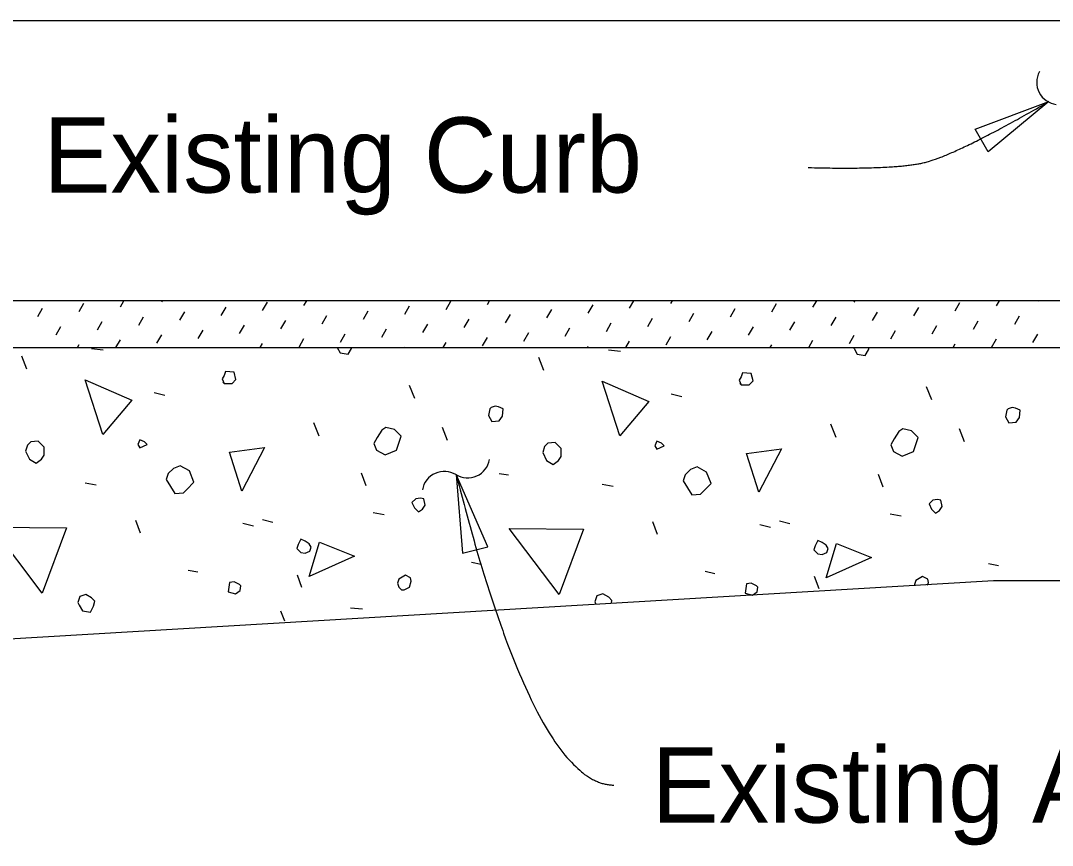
# Model space of a CAD drawing. Extents: x 0 to 41.1, y 0 to 25.9.
# Drawn here: x 29.229 to 31.992, y 5.252 to 7.46 of the extents above; entities that cross this region are included whole.
import ezdxf

# ---------------------------------------------------------------- set-up
doc = ezdxf.new("R2010")
doc.units = 0
for name, color, linetype in [('Dimension', 7, 'Continuous'), ('ExistSuperStruct', 7, 'Continuous'), ('Miscellaneous', 7, 'Continuous'), ('TextStructures', 7, 'Continuous')]:
    doc.layers.add(name, color=color, linetype=linetype)

msp = doc.modelspace()

# ---------------------------------------------------------------- linework, layer by layer
at = {"layer": 'Dimension'}
for points in [[(31.9826, 7.2434), (31.8199, 7.1087), (31.7846, 7.1698)], [(30.3947, 6.2447), (30.4118, 6.0341), (30.4801, 6.0515)]]:
    msp.add_lwpolyline(points, close=True, dxfattribs=at)
for centre, start, end in [((32.0093, 7.2949), 151.5267, 263.2539), ((30.4256, 6.2953), 238.4384, 350.1656), ((30.3632, 6.1937), 58.4384, 170.1656)]:
    msp.add_arc(centre, 0.0596, start, end, dxfattribs=at)
for points in [[(31.338, 7.0666), (31.5548, 7.0609), (31.7259, 7.0951), (31.9826, 7.2435)], [(30.3951, 6.2447), (30.6063, 5.4135), (30.8176, 5.4135)]]:
    msp.add_open_spline(points, degree=2, dxfattribs=at)
at = {"layer": 'ExistSuperStruct'}
for p, q in [((26.6139, 7.4599), (34.561, 7.4599)), ((37.3622, 6.71), (26.6139, 6.71)), ((26.6139, 6.585), (37.3622, 6.585)), ((31.8338, 5.9599), (27.6138, 5.7099)), ((37.3622, 5.9599), (31.8338, 5.9599))]:
    msp.add_line(p, q, dxfattribs=at)
at = {"layer": 'Miscellaneous'}
for p, q in [((29.2746, 6.6679), (29.2875, 6.6903)), ((29.3852, 6.6809), (29.3982, 6.7033)), ((29.4958, 6.6938), (29.5052, 6.71)), ((29.6065, 6.7068), (29.6083, 6.71)), ((29.7659, 6.6709), (29.7789, 6.6933)), ((29.8766, 6.6839), (29.8895, 6.7063)), ((29.9872, 6.6969), (29.9948, 6.71)), ((30.0978, 6.7098), (30.0979, 6.71)), ((30.2573, 6.6739), (30.2702, 6.6963)), ((30.3679, 6.6869), (30.3809, 6.7093)), ((30.4786, 6.6999), (30.4844, 6.71)), ((30.7487, 6.677), (30.7616, 6.6994)), ((30.8593, 6.6899), (30.8709, 6.71)), ((30.9699, 6.7029), (30.974, 6.71)), ((31.1294, 6.667), (31.1423, 6.6894)), ((31.24, 6.68), (31.253, 6.7024)), ((31.3506, 6.693), (31.3605, 6.71)), ((31.4613, 6.7059), (31.4637, 6.71)), ((31.6207, 6.67), (31.6337, 6.6924)), ((31.7314, 6.683), (31.7443, 6.7054)), ((31.842, 6.696), (31.8502, 6.71)), ((31.9526, 6.7089), (31.9533, 6.71)), ((29.5447, 6.645), (29.5576, 6.6674)), ((29.6553, 6.658), (29.6683, 6.6804)), ((30.036, 6.648), (30.049, 6.6704)), ((30.1467, 6.661), (30.1596, 6.6834)), ((30.4168, 6.6381), (30.4297, 6.6605)), ((30.5274, 6.651), (30.5403, 6.6734)), ((30.638, 6.664), (30.651, 6.6864)), ((30.9081, 6.6411), (30.9211, 6.6635)), ((31.0188, 6.6541), (31.0317, 6.6765)), ((31.3995, 6.6441), (31.4124, 6.6665)), ((31.5101, 6.6571), (31.5231, 6.6795)), ((31.8908, 6.6471), (31.9038, 6.6695)), ((29.3234, 6.6191), (29.3364, 6.6415)), ((29.434, 6.632), (29.447, 6.6544)), ((29.8148, 6.6221), (29.8277, 6.6445)), ((29.9254, 6.6351), (29.9384, 6.6574)), ((30.1955, 6.6121), (30.2085, 6.6345)), ((30.3061, 6.6251), (30.3191, 6.6475)), ((30.6869, 6.6152), (30.6998, 6.6376)), ((30.7975, 6.6281), (30.8104, 6.6505)), ((31.1782, 6.6182), (31.1912, 6.6406)), ((31.2889, 6.6312), (31.3018, 6.6535)), ((31.6696, 6.6212), (31.6825, 6.6436)), ((31.7802, 6.6342), (31.7932, 6.6566)), ((29.4839, 6.585), (29.4958, 6.6056)), ((29.5935, 6.5962), (29.6065, 6.6186)), ((29.7041, 6.6091), (29.7171, 6.6315)), ((29.9742, 6.5862), (29.9872, 6.6086)), ((30.0849, 6.5992), (30.0978, 6.6216)), ((30.4656, 6.5892), (30.4786, 6.6116)), ((30.5762, 6.6022), (30.5892, 6.6246)), ((30.957, 6.5923), (30.9699, 6.6147)), ((31.0676, 6.6052), (31.0805, 6.6276)), ((31.3392, 6.585), (31.3506, 6.6047)), ((31.4483, 6.5953), (31.4613, 6.6177)), ((31.559, 6.6082), (31.5719, 6.6306)), ((31.8291, 6.5853), (31.842, 6.6077)), ((31.9397, 6.5983), (31.9526, 6.6207)), ((29.3807, 6.585), (29.3852, 6.5926)), ((29.4182, 6.5825), (29.45, 6.579)), ((29.8704, 6.585), (29.8766, 6.5957)), ((30.2569, 6.585), (30.2573, 6.5857)), ((30.36, 6.585), (30.3679, 6.5987)), ((30.7465, 6.585), (30.7487, 6.5887)), ((30.8029, 6.579), (30.8347, 6.5755)), ((30.8496, 6.585), (30.8593, 6.6017)), ((31.2361, 6.585), (31.24, 6.5917)), ((31.7257, 6.585), (31.7314, 6.5948)), ((29.2456, 6.5266), (29.2314, 6.5619)), ((30.6302, 6.5231), (30.6161, 6.5584)), ((30.2844, 6.4482), (30.2702, 6.4835)), ((31.6691, 6.4446), (31.6549, 6.48)), ((29.5861, 6.4641), (29.6144, 6.457)), ((30.9708, 6.4606), (30.9991, 6.4535)), ((30.0281, 6.3474), (30.0139, 6.3828)), ((30.3721, 6.3357), (30.358, 6.371)), ((31.4127, 6.3439), (31.3986, 6.3792)), ((31.7568, 6.3321), (31.7427, 6.3675)), ((30.1536, 6.2148), (30.1412, 6.2484)), ((30.51, 6.2473), (30.5348, 6.2437)), ((31.5382, 6.2113), (31.5259, 6.2449)), ((29.4011, 6.2225), (29.4312, 6.2172)), ((30.7858, 6.219), (30.8159, 6.2137)), ((30.1724, 6.143), (30.2024, 6.1377)), ((31.5571, 6.1394), (31.5871, 6.1341)), ((29.5496, 6.0882), (29.5372, 6.1218)), ((29.8236, 6.1147), (29.8519, 6.1076)), ((29.876, 6.1247), (29.9043, 6.1176)), ((30.9343, 6.0846), (30.9219, 6.1182)), ((31.2083, 6.1112), (31.2366, 6.1041)), ((31.2607, 6.1211), (31.289, 6.1141)), ((30.4358, 6.0104), (30.4623, 6.0051)), ((31.8205, 6.0069), (31.847, 6.0016)), ((29.6769, 5.9892), (29.7034, 5.9839)), ((29.9821, 5.9421), (29.9697, 5.9757)), ((31.0616, 5.9857), (31.0881, 5.9803)), ((31.3668, 5.9385), (31.3544, 5.9721)), ((30.1123, 5.8884), (30.1441, 5.8849)), ((29.9361, 5.8525), (29.9255, 5.879))]:
    msp.add_line(p, q, dxfattribs=at)
for points in [[(30.0764, 6.585), (30.0846, 6.5702), (30.1058, 6.5666), (30.1147, 6.5825), (30.1153, 6.585)], [(31.4592, 6.585), (31.4605, 6.5825)], [(31.4605, 6.5825), (31.4693, 6.5666), (31.4905, 6.5631), (31.4994, 6.579), (31.5008, 6.585)], [(29.4489, 6.3516), (29.4011, 6.4983), (29.5266, 6.4435), (29.4489, 6.3516)], [(29.7735, 6.4888), (29.7947, 6.4888), (29.8053, 6.4994), (29.8, 6.5189), (29.777, 6.5207), (29.7735, 6.5101), (29.7682, 6.5012), (29.7735, 6.4888), (29.77, 6.4924)], [(30.8335, 6.348), (30.7858, 6.4948), (30.9113, 6.44), (30.8335, 6.348)], [(31.1582, 6.4853), (31.1794, 6.4853), (31.19, 6.4959), (31.1847, 6.5154), (31.1617, 6.5171), (31.1582, 6.5065), (31.1529, 6.4977), (31.1582, 6.4853), (31.1546, 6.4888)], [(30.4817, 6.4028), (30.4906, 6.3869), (30.51, 6.3887), (30.5189, 6.4011), (30.5206, 6.4205), (30.5083, 6.4258), (30.4994, 6.4276), (30.4888, 6.4241), (30.4853, 6.4205), (30.4817, 6.4028)], [(31.8664, 6.3993), (31.8753, 6.3834), (31.8947, 6.3852), (31.9035, 6.3975), (31.9053, 6.417), (31.8929, 6.4223), (31.8841, 6.4241), (31.8735, 6.4205), (31.87, 6.417), (31.8664, 6.3993)], [(30.1818, 6.3103), (30.2048, 6.2979), (30.2349, 6.3103), (30.2473, 6.3474), (30.2296, 6.3651), (30.2066, 6.3704), (30.196, 6.3633), (30.1836, 6.3439), (30.1748, 6.328), (30.1818, 6.3103)], [(31.5665, 6.3068), (31.5895, 6.2944), (31.6196, 6.3068), (31.6319, 6.3439), (31.6143, 6.3616), (31.5913, 6.3669), (31.5807, 6.3598), (31.5683, 6.3403), (31.5595, 6.3244), (31.5665, 6.3068)], [(29.242, 6.3074), (29.2526, 6.2862), (29.2703, 6.2756), (29.2844, 6.2862), (29.2915, 6.2968), (29.2915, 6.318), (29.2756, 6.3339), (29.2562, 6.3321), (29.2473, 6.3233), (29.242, 6.3074)], [(29.5478, 6.3162), (29.5673, 6.3251), (29.5602, 6.3321), (29.5478, 6.3374), (29.5425, 6.3251), (29.5478, 6.3162)], [(30.6267, 6.3039), (30.6373, 6.2826), (30.655, 6.272), (30.6691, 6.2826), (30.6762, 6.2932), (30.6762, 6.3145), (30.6603, 6.3304), (30.6408, 6.3286), (30.632, 6.3198), (30.6267, 6.3039)], [(30.9325, 6.3127), (30.952, 6.3215), (30.9449, 6.3286), (30.9325, 6.3339), (30.9272, 6.3215), (30.9325, 6.3127)], [(29.8212, 6.2007), (29.7876, 6.305), (29.8813, 6.3174), (29.8212, 6.2007)], [(31.2059, 6.1972), (31.1723, 6.3015), (31.266, 6.3138), (31.2059, 6.1972)], [(29.6186, 6.2314), (29.6415, 6.1942), (29.6645, 6.196), (29.6734, 6.2049), (29.6928, 6.2243), (29.6804, 6.2544), (29.6557, 6.2685), (29.638, 6.2614), (29.6239, 6.2473), (29.6186, 6.2314)], [(31.0032, 6.2278), (31.0262, 6.1907), (31.0492, 6.1925), (31.058, 6.2013), (31.0775, 6.2208), (31.0651, 6.2508), (31.0404, 6.265), (31.0227, 6.2579), (31.0085, 6.2437), (31.0032, 6.2278)], [(30.2838, 6.1554), (30.2944, 6.1448), (30.305, 6.1518), (30.312, 6.1624), (30.3085, 6.1801), (30.2997, 6.1819), (30.2873, 6.1801), (30.2767, 6.1695), (30.2838, 6.1554)], [(31.6684, 6.1518), (31.679, 6.1412), (31.6896, 6.1483), (31.6967, 6.1589), (31.6932, 6.1766), (31.6843, 6.1783), (31.672, 6.1766), (31.6614, 6.166), (31.6684, 6.1518)], [(29.2862, 5.9273), (29.1519, 6.1041), (29.3516, 6.1023), (29.2862, 5.9273)], [(30.6709, 5.9238), (30.5365, 6.1006), (30.7363, 6.0988), (30.6709, 5.9238)], [(29.9786, 6.0363), (29.9909, 6.0345), (30.0033, 6.0398), (30.0068, 6.0504), (30.0015, 6.0593), (29.9909, 6.0663), (29.9786, 6.0716), (29.9715, 6.0575), (29.9679, 6.0469), (29.9786, 6.0363)], [(30.0009, 5.9715), (30.0292, 6.0634), (30.1229, 6.0263), (30.0009, 5.9715)], [(31.3632, 6.0328), (31.3756, 6.031), (31.388, 6.0363), (31.3915, 6.0469), (31.3862, 6.0557), (31.3756, 6.0628), (31.3632, 6.0681), (31.3562, 6.054), (31.3526, 6.0434), (31.3632, 6.0328)], [(31.3856, 5.968), (31.4139, 6.0599), (31.5076, 6.0228), (31.3856, 5.968)], [(30.2484, 5.9362), (30.2555, 5.9362), (30.2696, 5.9432), (30.2749, 5.9591), (30.2731, 5.968), (30.259, 5.975), (30.2413, 5.9644), (30.2378, 5.9538), (30.2413, 5.9432), (30.2484, 5.9362)], [(31.6574, 5.9489), (31.6596, 5.9556), (31.6578, 5.9644), (31.6437, 5.9715), (31.626, 5.9609), (31.6225, 5.9503), (31.6236, 5.9468)], [(29.7847, 5.9309), (29.8042, 5.9255), (29.8165, 5.9344), (29.8183, 5.9468), (29.8148, 5.9503), (29.8006, 5.9574), (29.7883, 5.9556), (29.7865, 5.9432), (29.7847, 5.9309)], [(31.1694, 5.9273), (31.1889, 5.922), (31.2012, 5.9309), (31.203, 5.9432), (31.1995, 5.9468), (31.1853, 5.9538), (31.1729, 5.9521), (31.1712, 5.9397), (31.1694, 5.9273)], [(29.3852, 5.8955), (29.3941, 5.8796), (29.4153, 5.8761), (29.4241, 5.892), (29.4276, 5.9061), (29.4188, 5.9149), (29.4029, 5.9238), (29.387, 5.9185), (29.3817, 5.9026), (29.3852, 5.8955)], [(30.8107, 5.9012), (30.8123, 5.9078), (30.8035, 5.9166), (30.7876, 5.9254), (30.7717, 5.9201), (30.7664, 5.9042), (30.7692, 5.8986)]]:
    msp.add_lwpolyline(points, dxfattribs=at)

# ---------------------------------------------------------------- texts
at = {"layer": 'TextStructures'}
for s, p in [('Existing Curb', (29.2896, 6.9996)), ('Existing Approach Slab', (30.9186, 5.3129))]:
    msp.add_text(s, height=0.2016, dxfattribs=at).set_placement(p)

doc.saveas('drawing.dxf')
